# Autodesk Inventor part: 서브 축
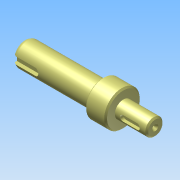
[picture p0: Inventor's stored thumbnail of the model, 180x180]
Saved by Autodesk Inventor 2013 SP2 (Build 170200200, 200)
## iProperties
Created: 2026-07
Part Number: 서브 축
Material: Generic
Document SubType Name: Modeling
Designer: 601
Density: 1 g/cm^3
Author: 601
변환 표준: STEP AP214IS
전처리기: Build: 200, Release: 2013 SP2 Update 6 - Date: Thu 07/17/2014
전송 단위: 밀리미터
불확실성: 0.01
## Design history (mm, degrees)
node "서브 축1"
node "솔리드1"
node "기준1"
